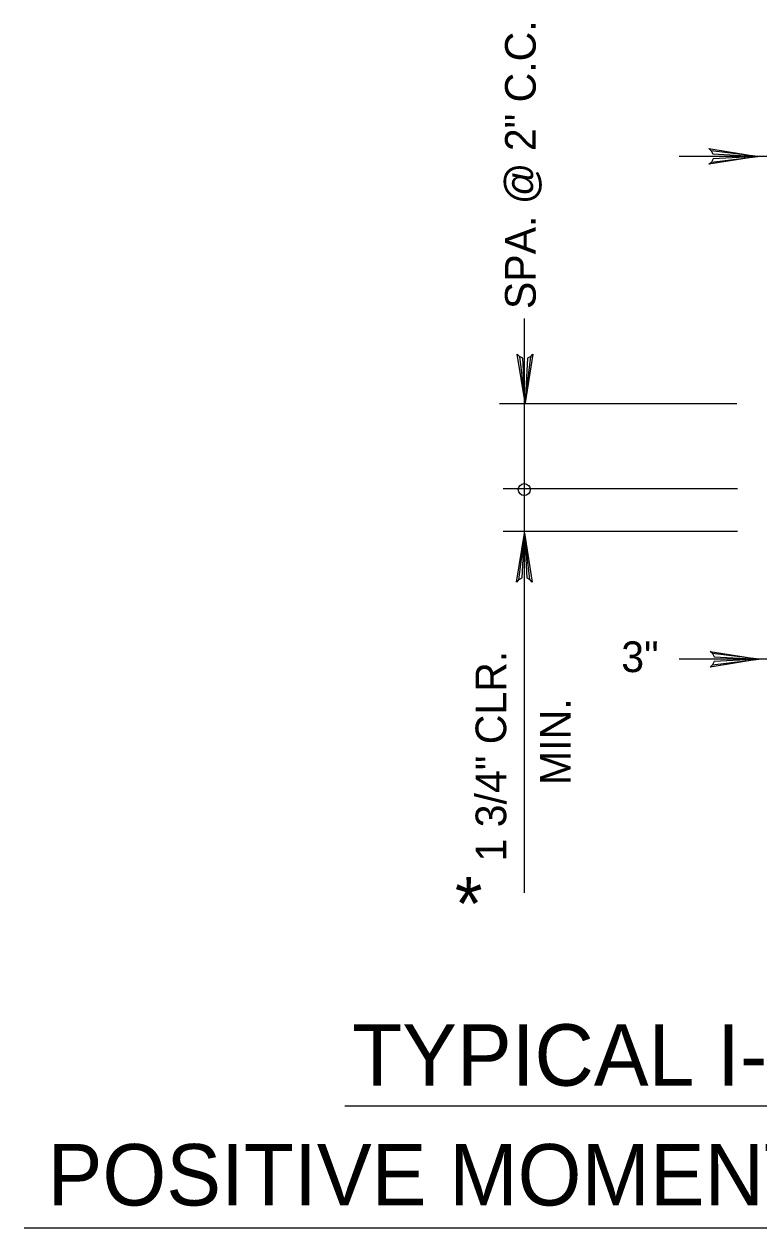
# Model space of a CAD drawing. Extents: x 639980 to 641204, y 298038 to 300414.
# Drawn here: x 640274.3 to 640346.1, y 298817.1 to 298934.7 of the extents above; entities that cross this region are included whole.
import ezdxf

# ---------------------------------------------------------------- set-up
doc = ezdxf.new("R2010")
doc.units = 0
doc.layers.add('2', color=7, linetype='Continuous')
doc.layers.add('3', color=7, linetype='Continuous')

msp = doc.modelspace()

# ---------------------------------------------------------------- linework, layer by layer
at = {"layer": '2'}
for p, q in [((640323.21, 298901.73), (640323.21, 298905.92)), ((640323.21, 298889.29), (640323.21, 298901.73)), ((640343.97, 298897.59), (640320.76, 298897.59)), ((640344.04, 298889.29), (640321.13, 298889.29)), ((640323.21, 298849.82), (640323.21, 298889.29)), ((640344.04, 298885.13), (640321.13, 298885.13)), ((640413.87, 298872.63), (640338.34, 298872.63)), ((640305.65, 298829.02), (640435.83, 298829.02)), ((640274.32, 298817.09), (640467.16, 298817.09))]:
    msp.add_line(p, q, dxfattribs=at)
at = {"layer": '3'}
msp.add_line((640413.87, 298921.74), (640338.34, 298921.74), dxfattribs=at)
for points in [[(640341.46, 298922.31), (640341.63, 298921.99), (640346, 298921.74), (640341.46, 298922.31), (640341.23, 298922.51), (640346, 298921.74), (640341.64, 298921.53), (640341.48, 298921.2), (640346, 298921.74), (640341.23, 298920.99), (640341.48, 298921.2)], [(640323.84, 298902.22), (640323.51, 298902.05), (640323.27, 298897.68), (640323.84, 298902.22), (640324.04, 298902.45), (640323.27, 298897.68), (640323.05, 298902.05), (640322.73, 298902.21), (640323.27, 298897.68), (640322.51, 298902.45), (640322.73, 298902.21)], [(640322.64, 298880.4), (640322.97, 298880.58), (640323.21, 298884.95), (640322.64, 298880.4), (640322.44, 298880.17), (640323.21, 298884.95), (640323.43, 298880.58), (640323.75, 298880.42), (640323.21, 298884.95), (640323.97, 298880.17), (640323.75, 298880.42)], [(640341.58, 298873.2), (640341.75, 298872.87), (640346.12, 298872.63), (640341.58, 298873.2), (640341.34, 298873.4), (640346.12, 298872.63), (640341.75, 298872.41), (640341.59, 298872.09), (640346.12, 298872.63), (640341.34, 298871.87), (640341.59, 298872.09)]]:
    msp.add_lwpolyline(points, dxfattribs=at)
msp.add_circle((640323.19, 298889.21), 0.584, dxfattribs=at)

# ---------------------------------------------------------------- texts
at = {"layer": '2'}
for s, p in [('TYPICAL I-BEAM SECTION', (640306.36, 298830.98)), ('POSITIVE MOMENT REINF. LOCATIONS', (640276.62, 298819.28))]:
    msp.add_text(s, height=6, dxfattribs=at).set_placement(p)
at = {"layer": '3'}
for s, height, p in [('SPA. @ 2" C.C.', 2.9968, (640324.31, 298906.84)), ('1 3/4" CLR.', 2.9978, (640321.43, 298852.88)), ('MIN.', 2.998, (640327.73, 298860.35))]:
    msp.add_text(s, height=height, rotation=90, dxfattribs=at).set_placement(p)
for s, height, p in [('3"', 2.997, (640332.67, 298871.38)), ('*', 5.18, (640316.41, 298846.18))]:
    msp.add_text(s, height=height, dxfattribs=at).set_placement(p)

doc.saveas('drawing.dxf')
